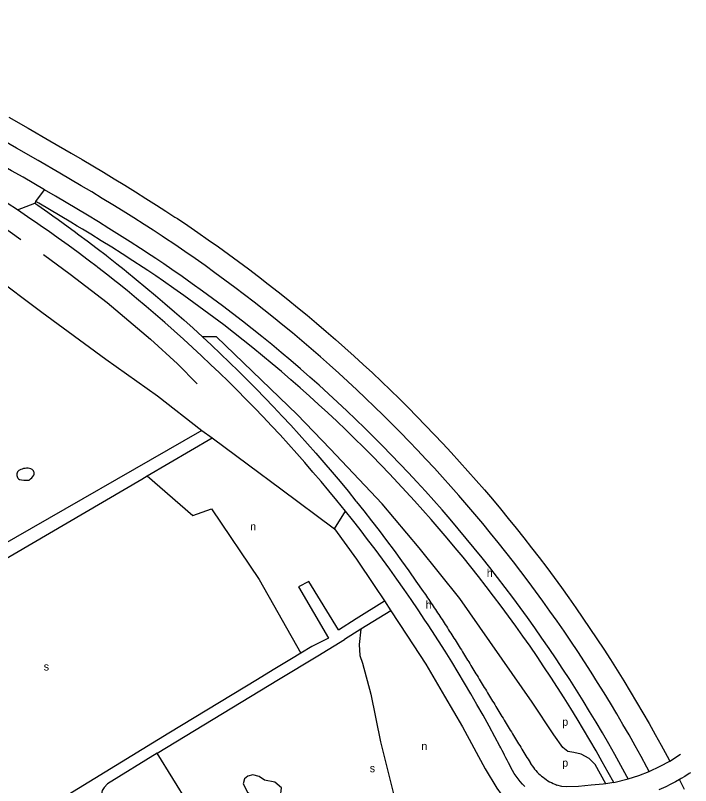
# Model space of a CAD drawing. Extents: x 156066 to 157805, y 383432 to 385631.
# Drawn here: x 157390.3 to 157728, y 384446.9 to 384832 of the extents above; entities that cross this region are included whole.
import ezdxf

# ---------------------------------------------------------------- set-up
doc = ezdxf.new("R2010")
doc.units = 0
for name, color, linetype in [('BLT_Basislijn', 7, 'Continuous'), ('BLT_Centroide', 7, 'Continuous'), ('BLT_Vlakafsluiter', 7, 'Continuous')]:
    doc.layers.add(name, color=color, linetype=linetype)

msp = doc.modelspace()

# ---------------------------------------------------------------- linework, layer by layer
at = {"layer": 'BLT_Basislijn'}
for p, q in [((157483.49, 384624.52), (157365.92, 384557.05)), ((157483.49, 384624.52), (157488.69, 384620.75)), ((157456.25, 384601.79), (157488.69, 384620.75)), ((157453.47, 384600.17), (157456.25, 384601.79)), ((157574.94, 384539.23), (157577.97, 384534.34)), ((157577.97, 384534.34), (157563.05, 384525.09)), ((157563.05, 384525.09), (157554.82, 384519.99)), ((157541.48, 384511.88), (157554.82, 384519.99)), ((157538.48, 384516.49), (157533.02, 384513.18)), ((157528.29, 384510.31), (157519.14, 384504.76)), ((157521.93, 384500), (157541.48, 384511.88)), ((157533.02, 384513.18), (157528.29, 384510.31)), ((157519.14, 384504.76), (157511.3, 384500)), ((157461.24, 384463.14), (157521.93, 384500)), ((157522.22, 384364.48), (157461.24, 384463.14)), ((157717.53, 384459.22), (157722.96, 384462.63)), ((157707.25, 384454.05), (157712.83, 384456.67)), ((157712.83, 384456.67), (157717.53, 384459.22)), ((157696.75, 384450.26), (157702.1, 384452.02)), ((157702.1, 384452.02), (157707.25, 384454.05)), ((157689.52, 384448.4), (157696.75, 384450.26))]:
    msp.add_line(p, q, dxfattribs=at)
for points in [[(157391.26, 384734.71), (157386.09, 384738.11), (157380.89, 384741.46), (157375.97, 384744.58), (157367.23, 384749.96), (157365.32, 384751.12), (157354.55, 384757.47), (157343.7, 384763.69), (157332.84, 384769.92), (157321.99, 384776.15), (157311.14, 384782.41), (157300.3, 384788.68), (157289.47, 384794.99), (157278.65, 384801.32), (157267.85, 384807.68), (157257.06, 384814.09), (157246.29, 384820.53), (157235.54, 384827.01), (157224.81, 384833.55)], [(157404.89, 384744.78), (157394.08, 384751.05), (157388.35, 384754.34), (157383.23, 384757.27), (157374.32, 384762.37), (157372.38, 384763.48), (157361.53, 384769.68), (157350.68, 384775.89), (157339.84, 384782.1), (157329, 384788.33), (157318.17, 384794.57), (157307.35, 384800.84), (157296.55, 384807.12), (157285.76, 384813.43), (157274.99, 384819.78), (157264.25, 384826.16), (157253.52, 384832.57)], [(157214.85, 384825.93), (157233.41, 384815.26), (157270.01, 384793.38), (157298.55, 384776.89), (157329.77, 384758.86), (157364.24, 384738.95), (157383.47, 384726.72), (157393.03, 384719.99)], [(157386.91, 384781.09), (157396.58, 384775.56), (157407.42, 384769.34), (157418.22, 384763.08), (157423.6, 384759.93), (157428.98, 384756.76), (157434.33, 384753.56), (157439.68, 384750.34), (157445, 384747.1), (157450.3, 384743.82), (157455.58, 384740.52), (157460.84, 384737.17), (157465.47, 384734.18), (157470.08, 384731.16), (157471.27, 384730.37), (157476.45, 384726.91), (157481.59, 384723.4), (157486.71, 384719.85), (157491.79, 384716.26), (157496.85, 384712.62), (157501.88, 384708.94), (157506.87, 384705.23), (157511.83, 384701.47), (157516.76, 384697.66), (157521.66, 384693.82), (157526.53, 384689.94), (157531.37, 384686.02), (157536.17, 384682.05), (157540.94, 384678.05), (157545.67, 384674.01), (157550.38, 384669.92), (157555.04, 384665.8), (157559.68, 384661.64), (157564.27, 384657.44), (157568.84, 384653.21), (157573.37, 384648.93), (157577.86, 384644.62), (157582.31, 384640.27), (157586.73, 384635.88), (157591.11, 384631.46), (157595.46, 384627), (157599.77, 384622.51), (157604.04, 384617.97), (157608.27, 384613.41), (157612.47, 384608.81), (157616.62, 384604.17), (157620.74, 384599.5), (157624.82, 384594.79), (157628.86, 384590.05), (157632.86, 384585.28), (157636.82, 384580.48), (157640.73, 384575.64), (157644.61, 384570.77), (157648.45, 384565.86), (157652.25, 384560.93), (157656, 384555.96), (157659.72, 384550.96), (157663.39, 384545.94), (157667.02, 384540.88), (157670.61, 384535.79), (157674.15, 384530.67), (157677.66, 384525.52), (157681.12, 384520.34), (157684.53, 384515.14), (157687.91, 384509.9), (157691.24, 384504.64), (157694.52, 384499.35), (157697.76, 384494.04), (157700.96, 384488.69), (157704.11, 384483.32), (157707.22, 384477.93), (157710.28, 384472.51), (157713.3, 384467.06), (157716.27, 384461.59), (157717.53, 384459.22)], [(157707.25, 384454.05), (157706.14, 384456.14), (157703.21, 384461.53), (157700.24, 384466.89), (157697.23, 384472.23), (157694.17, 384477.54), (157691.07, 384482.83), (157687.92, 384488.09), (157684.73, 384493.33), (157681.49, 384498.53), (157678.21, 384503.72), (157674.89, 384508.87), (157671.53, 384513.99), (157668.12, 384519.09), (157664.67, 384524.16), (157661.18, 384529.2), (157657.65, 384534.21), (157654.08, 384539.19), (157650.46, 384544.14), (157646.8, 384549.06), (157643.1, 384553.95), (157639.37, 384558.81), (157635.59, 384563.64), (157631.77, 384568.44), (157627.91, 384573.2), (157624.01, 384577.93), (157620.07, 384582.63), (157616.1, 384587.3), (157612.08, 384591.93), (157608.03, 384596.53), (157603.94, 384601.09), (157599.81, 384605.63), (157595.64, 384610.12), (157591.43, 384614.58), (157587.19, 384619.01), (157582.91, 384623.4), (157578.6, 384627.76), (157574.25, 384632.08), (157569.86, 384636.36), (157565.44, 384640.6), (157560.98, 384644.81), (157556.49, 384648.98), (157551.96, 384653.12), (157547.4, 384657.21), (157542.8, 384661.27), (157538.17, 384665.29), (157533.51, 384669.27), (157528.81, 384673.21), (157524.08, 384677.12), (157519.32, 384680.98), (157514.53, 384684.8), (157509.71, 384688.59), (157504.85, 384692.33), (157499.96, 384696.03), (157495.05, 384699.69), (157490.1, 384703.31), (157485.12, 384706.89), (157480.11, 384710.43), (157475.08, 384713.92), (157470.01, 384717.38), (157464.92, 384720.79), (157463.74, 384721.57), (157459.2, 384724.54), (157454.63, 384727.49), (157449.45, 384730.79), (157444.23, 384734.06), (157438.99, 384737.3), (157433.72, 384740.51), (157428.42, 384743.7), (157423.11, 384746.86), (157417.78, 384750.01), (157412.42, 384753.15), (157401.67, 384759.38), (157390.87, 384765.58), (157381.21, 384771.11)], [(157696.75, 384450.26), (157696.12, 384451.44), (157693.13, 384456.94), (157690.09, 384462.4), (157687.01, 384467.84), (157683.87, 384473.26), (157680.7, 384478.64), (157677.47, 384484), (157674.2, 384489.33), (157670.89, 384494.64), (157667.52, 384499.91), (157664.12, 384505.15), (157660.67, 384510.37), (157657.17, 384515.55), (157653.63, 384520.71), (157650.04, 384525.83), (157646.41, 384530.92), (157642.74, 384535.98), (157639.02, 384541.01), (157635.26, 384546.01), (157631.45, 384550.97), (157627.61, 384555.9), (157623.72, 384560.8), (157619.79, 384565.67), (157615.81, 384570.5), (157611.8, 384575.29), (157607.74, 384580.05), (157603.65, 384584.78), (157599.51, 384589.47), (157595.33, 384594.12), (157591.12, 384598.74), (157586.86, 384603.32), (157582.56, 384607.86), (157578.23, 384612.37), (157573.85, 384616.84), (157569.44, 384621.27), (157564.99, 384625.66), (157560.5, 384630.02), (157555.97, 384634.33), (157551.41, 384638.61), (157546.81, 384642.85), (157542.17, 384647.05), (157537.5, 384651.2), (157532.79, 384655.32), (157528.05, 384659.39), (157523.27, 384663.43), (157518.46, 384667.42), (157513.61, 384671.37), (157508.73, 384675.28), (157503.82, 384679.15), (157498.87, 384682.98), (157493.89, 384686.76), (157488.87, 384690.5), (157483.83, 384694.19), (157478.75, 384697.84), (157473.64, 384701.45), (157468.5, 384705.01), (157464.54, 384707.72), (157460.55, 384710.4), (157458.13, 384712.01), (157452.9, 384715.44), (157447.65, 384718.83), (157442.37, 384722.18), (157437.07, 384725.49), (157431.75, 384728.77), (157426.4, 384732.03), (157421.05, 384735.25), (157415.68, 384738.45), (157410.29, 384741.62), (157404.89, 384744.78)], [(157400.43, 384738.99), (157399.93, 384738.12)], [(157399.93, 384738.12), (157401.41, 384737.11), (157406.54, 384733.54), (157409.01, 384731.8), (157411.65, 384729.93), (157416.72, 384726.27), (157419.66, 384724.12), (157422.06, 384722.31), (157426.11, 384719.3), (157431.1, 384715.52), (157435.6, 384712.05), (157436.05, 384711.71), (157440.97, 384707.85), (157444.6, 384704.97), (157445.86, 384703.95), (157450.72, 384700.01), (157455.54, 384696.03), (157460.34, 384692.01), (157465.09, 384687.96), (157469.82, 384683.86), (157474.51, 384679.72), (157479.16, 384675.54), (157483.78, 384671.33)], [(157689.52, 384448.4), (157686.77, 384453.44), (157683.77, 384458.85), (157680.71, 384464.24), (157677.61, 384469.6), (157674.47, 384474.93), (157671.28, 384480.24), (157668.04, 384485.52), (157664.76, 384490.76), (157661.43, 384495.99), (157658.06, 384501.18), (157654.64, 384506.34), (157651.18, 384511.47), (157647.67, 384516.57), (157644.12, 384521.65), (157640.52, 384526.69), (157636.89, 384531.7), (157633.21, 384536.68), (157629.48, 384541.62), (157625.72, 384546.54), (157621.91, 384551.42), (157618.06, 384556.27), (157614.17, 384561.08), (157610.24, 384565.87), (157606.26, 384570.61), (157602.25, 384575.33), (157598.19, 384580), (157594.09, 384584.65), (157589.96, 384589.25), (157585.78, 384593.83), (157581.57, 384598.36), (157577.31, 384602.86), (157573.02, 384607.32), (157568.69, 384611.75), (157564.32, 384616.13), (157559.92, 384620.48), (157555.47, 384624.79), (157550.99, 384629.07), (157546.47, 384633.3), (157541.92, 384637.49), (157537.33, 384641.65), (157532.71, 384645.76), (157528.04, 384649.84), (157523.35, 384653.88), (157518.62, 384657.87), (157513.85, 384661.82), (157509.05, 384665.73), (157504.22, 384669.61), (157499.36, 384673.43), (157494.46, 384677.22), (157489.53, 384680.96), (157484.56, 384684.67), (157479.57, 384688.32), (157474.54, 384691.94), (157469.49, 384695.51), (157464.4, 384699.04), (157460.47, 384701.72), (157456.52, 384704.37), (157454.13, 384705.96), (157448.95, 384709.36), (157443.74, 384712.72), (157438.51, 384716.04), (157433.24, 384719.33), (157427.96, 384722.59), (157423.77, 384725.14), (157421.2, 384726.69), (157418.02, 384728.61), (157412.68, 384731.79), (157407.32, 384734.96), (157401.95, 384738.11), (157400.43, 384738.99)], [(157555.31, 384584.21), (157551.05, 384589.46), (157547.11, 384594.24), (157543.13, 384598.99), (157539.11, 384603.7), (157535.06, 384608.38), (157530.96, 384613.02), (157526.82, 384617.63), (157522.65, 384622.21), (157518.44, 384626.75), (157514.19, 384631.26), (157509.9, 384635.73), (157505.58, 384640.16), (157501.22, 384644.56), (157496.82, 384648.92), (157496.82, 384648.92), (157492.39, 384653.24), (157487.92, 384657.53), (157483.41, 384661.78), (157478.87, 384665.99), (157474.3, 384670.17), (157469.69, 384674.3), (157465.04, 384678.4), (157460.36, 384682.45), (157455.64, 384686.47), (157450.89, 384690.44), (157446.1, 384694.37), (157441.28, 384698.25), (157440.02, 384699.25), (157436.42, 384702.1), (157431.54, 384705.9), (157431.09, 384706.24), (157426.61, 384709.65), (157421.66, 384713.37), (157416.67, 384717.04), (157411.65, 384720.66), (157406.6, 384724.24), (157403.83, 384726.17), (157401.52, 384727.78), (157396.4, 384731.27), (157391.26, 384734.71)], [(157404.24, 384712.49), (157417.69, 384702.56), (157436.09, 384688.5), (157457.8, 384670.15), (157471.37, 384657.74), (157481.18, 384647.78)], [(157378.55, 384702.32), (157403.46, 384683.56), (157435.54, 384660.17), (157461.32, 384641.74), (157483.49, 384624.52)], [(157483.78, 384671.33), (157488.37, 384667.07), (157492.91, 384662.78), (157497.43, 384658.45), (157501.9, 384654.09), (157501.91, 384654.09), (157506.34, 384649.68), (157510.75, 384645.24), (157515.11, 384640.77), (157519.44, 384636.25), (157523.73, 384631.7), (157527.99, 384627.12), (157532.2, 384622.5), (157536.38, 384617.84), (157540.51, 384613.15), (157544.61, 384608.43), (157548.67, 384603.67), (157552.69, 384598.88), (157556.67, 384594.05), (157560.6, 384589.19), (157560.96, 384588.75), (157564.5, 384584.3), (157568.36, 384579.38), (157572.17, 384574.43), (157575.95, 384569.44), (157579.68, 384564.42), (157583.37, 384559.37), (157587.02, 384554.29), (157590.62, 384549.18), (157594.19, 384544.04), (157594.75, 384543.22), (157595.32, 384542.39), (157595.88, 384541.57), (157596.44, 384540.74), (157597, 384539.91), (157597.57, 384539.08), (157598.12, 384538.25), (157598.68, 384537.42), (157599.24, 384536.59), (157599.8, 384535.76), (157600.35, 384534.93), (157600.91, 384534.09), (157601.46, 384533.26), (157602.01, 384532.42), (157602.56, 384531.59), (157603.11, 384530.75), (157603.66, 384529.92), (157604.21, 384529.08), (157604.75, 384528.24), (157605.3, 384527.4), (157605.84, 384526.56), (157606.38, 384525.72), (157606.92, 384524.88), (157607.47, 384524.04), (157608, 384523.19), (157608.54, 384522.35), (157609.08, 384521.51), (157609.62, 384520.66), (157610.15, 384519.82), (157610.68, 384518.97), (157611.22, 384518.12), (157611.75, 384517.27), (157612.28, 384516.43), (157612.81, 384515.58), (157613.34, 384514.73), (157613.86, 384513.88), (157614.39, 384513.02), (157614.91, 384512.17), (157615.44, 384511.32), (157615.96, 384510.47), (157616.48, 384509.61), (157616.54, 384509.52), (157617, 384508.76), (157617.52, 384507.9), (157618.04, 384507.05), (157618.56, 384506.2), (157619.08, 384505.34), (157619.6, 384504.49), (157620.12, 384503.63), (157620.64, 384502.78), (157621.16, 384501.93), (157621.68, 384501.07), (157622.2, 384500.22), (157622.73, 384499.36), (157623.25, 384498.51), (157623.77, 384497.66), (157624.29, 384496.8), (157624.81, 384495.95), (157625.33, 384495.09), (157625.85, 384494.24), (157626.37, 384493.39), (157626.89, 384492.53), (157627.41, 384491.68), (157627.93, 384490.82), (157628.45, 384489.97), (157628.97, 384489.12), (157629.49, 384488.26), (157630.01, 384487.41), (157630.53, 384486.55), (157631.05, 384485.7), (157631.57, 384484.85), (157632.09, 384483.99), (157632.61, 384483.14), (157633.13, 384482.28), (157633.65, 384481.43), (157634.17, 384480.58), (157634.69, 384479.72), (157635.21, 384478.87), (157635.73, 384478.01), (157636.25, 384477.16), (157636.77, 384476.31), (157637.29, 384475.45), (157637.81, 384474.6), (157638.33, 384473.74), (157638.85, 384472.89), (157639.37, 384472.04), (157639.89, 384471.18), (157640.41, 384470.33), (157640.94, 384469.47), (157641.46, 384468.62), (157641.98, 384467.77), (157642.5, 384466.91), (157643.02, 384466.06), (157643.54, 384465.2), (157644.06, 384464.35), (157644.58, 384463.5), (157645.1, 384462.64), (157645.62, 384461.79), (157646.14, 384460.93), (157646.66, 384460.08), (157647.18, 384459.23), (157647.68, 384458.41), (157647.7, 384458.37), (157648.23, 384457.54), (157648.78, 384456.73), (157649.37, 384455.94), (157649.99, 384455.18), (157650.63, 384454.43), (157651.3, 384453.71), (157651.99, 384453.01), (157652.71, 384452.34), (157653.45, 384451.69), (157654.22, 384451.08), (157655, 384450.49), (157655.81, 384449.93), (157656.64, 384449.39), (157657.49, 384448.89), (157658.35, 384448.42), (157659.23, 384447.98), (157660.13, 384447.58), (157661.04, 384447.2)], [(157685.58, 384447.87), (157680.25, 384457.46), (157677.2, 384460.56), (157673.19, 384462.7), (157669.55, 384463.4), (157666.66, 384464.04), (157664.09, 384466.02), (157659.66, 384472.28), (157648.71, 384488.58), (157612.63, 384540.44), (157592.15, 384565.84), (157573.79, 384587.81), (157547.75, 384615.28), (157531.27, 384632.51), (157490.9, 384671.22)], [(157488.69, 384620.75), (157506.78, 384607.3), (157522.97, 384595.23), (157549.91, 384575.37)], [(157392.01, 384604.45), (157391.68, 384604.12), (157391.4, 384603.73), (157391.19, 384603.31), (157391.05, 384602.85), (157390.99, 384602.38), (157391.02, 384601.91), (157391.12, 384601.45), (157391.3, 384601.01), (157391.55, 384600.6), (157391.86, 384600.25), (157392.3, 384599.9)], [(157393.59, 384605.12), (157392.98, 384604.93), (157392.4, 384604.67), (157392.01, 384604.45)], [(157398, 384605.31), (157397.29, 384605.49), (157396.57, 384605.58), (157395.84, 384605.6), (157395.12, 384605.53), (157394.4, 384605.39), (157393.71, 384605.17), (157393.59, 384605.12)], [(157397.14, 384599.71), (157397.81, 384600.23), (157398.44, 384600.82), (157399.01, 384601.46), (157399.48, 384602.1)], [(157399.48, 384602.1), (157399.6, 384602.53), (157399.64, 384602.98), (157399.6, 384603.42), (157399.48, 384603.85), (157399.29, 384604.25), (157399.02, 384604.61), (157398.7, 384604.92), (157398.33, 384605.16), (157398, 384605.31)], [(157336.87, 384531.91), (157369.89, 384551.32), (157453.47, 384600.17)], [(157392.3, 384599.9), (157393.35, 384599.72), (157394.42, 384599.61), (157395.49, 384599.59), (157396.55, 384599.64), (157397.14, 384599.71)], [(157456.25, 384601.79), (157479.08, 384582.01), (157488.38, 384585.32), (157512.19, 384550.04), (157533.02, 384513.18)], [(157645.07, 384446.42), (157643.89, 384447.64), (157642.76, 384448.92), (157641.7, 384450.25), (157640.7, 384451.63), (157639.76, 384453.05), (157638.89, 384454.52), (157638.15, 384455.9), (157637.52, 384457.14), (157636.88, 384458.38), (157636.25, 384459.61), (157635.61, 384460.85), (157634.97, 384462.08), (157634.33, 384463.31), (157633.68, 384464.54), (157633.04, 384465.77), (157632.54, 384466.71), (157630.12, 384471.24), (157627.17, 384476.68), (157624.16, 384482.1), (157621.12, 384487.49), (157618.02, 384492.86), (157614.89, 384498.2), (157611.7, 384503.51), (157608.48, 384508.8), (157605.21, 384514.06), (157601.9, 384519.29), (157598.54, 384524.49), (157596.71, 384527.29), (157595.14, 384529.67), (157591.7, 384534.82), (157588.21, 384539.94), (157584.68, 384545.03), (157581.11, 384550.09), (157577.5, 384555.12), (157573.84, 384560.12), (157570.15, 384565.09), (157566.41, 384570.03), (157562.63, 384574.93), (157558.81, 384579.81), (157555.31, 384584.21)], [(157549.91, 384575.37), (157560.89, 384560.15), (157569.66, 384546.96), (157574.94, 384539.23)], [(157551.94, 384524.74), (157537.1, 384548.9), (157531.85, 384546.28), (157546.88, 384520.72), (157538.48, 384516.49)], [(157551.94, 384524.74), (157560.69, 384530.44), (157574.94, 384539.23)], [(157577.97, 384534.34), (157586.11, 384522.12), (157595.63, 384507.58), (157604.85, 384491.61), (157613.92, 384476.32), (157625.31, 384455.34), (157631.08, 384445.59), (157637.62, 384436.63)], [(157563.05, 384525.09), (157562.14, 384517.39), (157562.53, 384511.91), (157563.85, 384508.09), (157567.99, 384492.58), (157572.95, 384468.76), (157580.92, 384436.73), (157589.99, 384428.45), (157588.98, 384406.1)], [(157511.3, 384500), (157466.93, 384473.08), (157321.03, 384383.89)], [(157461.24, 384463.14), (157436.28, 384447.8), (157434.62, 384446.05), (157433.67, 384444.46), (157433.38, 384442.61), (157433.51, 384439.9), (157436.22, 384434.71), (157468.2, 384383.41), (157464.98, 384381.42), (157469.68, 384375.15)], [(157727.99, 384453.37), (157727.31, 384452.91), (157725.05, 384451.49), (157723.33, 384450.46), (157722.75, 384450.12), (157722.4, 384449.93)], [(157685.58, 384447.87), (157684.2, 384447.69), (157678.27, 384447.2), (157671.88, 384446.56), (157666.07, 384446.28), (157663.66, 384446.56), (157661.04, 384447.2)], [(157689.52, 384448.4), (157685.58, 384447.87)], [(157722.4, 384449.93), (157720.43, 384448.82), (157718.07, 384447.57), (157715.68, 384446.38), (157713.26, 384445.25), (157712.13, 384444.75)], [(157724.91, 384445.03), (157722.4, 384449.93)]]:
    msp.add_lwpolyline(points, dxfattribs=at)
msp.add_lwpolyline([(157514.8, 384449.69), (157512.15, 384451.46), (157509.05, 384452.27), (157506.55, 384451.69), (157504.89, 384450.38), (157504.16, 384447.78), (157506.31, 384443.71), (157511.27, 384439.83), (157515.36, 384438.64), (157520.56, 384439.23), (157522.84, 384441.4), (157523.35, 384445.86), (157519.96, 384448.66)], close=True, dxfattribs=at)
at = {"layer": 'BLT_Vlakafsluiter'}
for p, q in [((157400.43, 384738.99), (157404.89, 384744.78)), ((157391.26, 384734.71), (157399.93, 384738.12)), ((157490.9, 384671.22), (157483.78, 384671.33)), ((157549.91, 384575.37), (157555.31, 384584.21))]:
    msp.add_line(p, q, dxfattribs=at)

# ---------------------------------------------------------------- texts
at = {"layer": 'BLT_Centroide'}
for s, p in [('n', (157507.69, 384574.47)), ('h', (157626.05, 384551.25)), ('h', (157595.41, 384535.35)), ('s', (157404.44, 384504.44)), ('p', (157663.78, 384476.83)), ('p', (157663.77, 384456.36)), ('s', (157567.52, 384453.62))]:
    msp.add_text(s, height=4, dxfattribs=at).set_placement(p)
msp.add_text('n', height=4, rotation=359, dxfattribs=at).set_placement((157593.29, 384464.72))

doc.saveas('drawing.dxf')
